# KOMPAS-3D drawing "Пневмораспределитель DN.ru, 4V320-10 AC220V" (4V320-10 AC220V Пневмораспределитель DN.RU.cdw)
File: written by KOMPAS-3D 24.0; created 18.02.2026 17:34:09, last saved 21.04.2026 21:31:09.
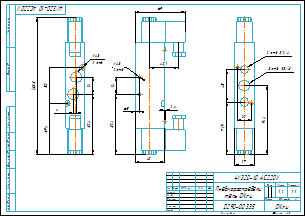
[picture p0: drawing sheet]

Document properties: Автор: R2D2; Форматы листов документа: A3; Полное имя файла: 4V320-10 AC220V Пневмораспределитель DN.RU.m3d; Масса: 1.2; Наименование: Пневмораспределитель DN.ru; Количество листов документа: 1; Примечание: D290-00335

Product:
- Body: Тело 1  | qty 1
    Масса: 1.552409
- Body: Тело 3  | qty 1
    Масса: 1.552409
- Part/product: Пневмораспределитель DN.ru  | designation 4V320-10 AC220V
    Масса: 1.2
    Раздел спецификации: Прочие изделия
    Примечание: D290-00335

Views: Вид 1, Спереди, Проекционный вид 2, Проекционный вид 3
Referenced files in E:\Работа\Зайцев\Аксессуары для пневмоприводов\Пневмораспределители DN.ru\4V320 AC220V Пневмораспределитель DN.RU\4V320-08 AC220V Пневмораспределитель DN.RU\: 4V320-08 AC220V Пневмораспределитель DN.RU.m3d
Referenced files in E:\Работа\Зайцев\Аксессуары для пневмоприводов\Пневмораспределители DN.ru\4V320 AC220V Пневмораспределитель DN.RU\4V320-10 AC220V Пневмораспределитель DN.RU\: 4V320-10 AC220V Пневмораспределитель DN.RU.m3d
Referenced files in E:\Работа\Зайцев\Для компаса\: чертеж DN.ru А3.cdt
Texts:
  чертеж DN.ru А3.cdt
  Пневмораспредели
  тель DN.ru
  пазы
  Пневмораспределитель DN.ru
  4V320-10 AC220V Пневмораспределитель DN.ru
Dimensions and other numbers on the sheet: 0; 3; 2; 4; 94,4; 71,9; 45; 27; 2 отв. G1/4'; 20; 3 отв. G3/8'; 4V320-10 AC220V; 4,3; 2 отв.; 69; 40,1; 82,4; 24; 40; 6,5; 2,4; 50; 188,8; 69,4; 1:1; 1; 1,2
